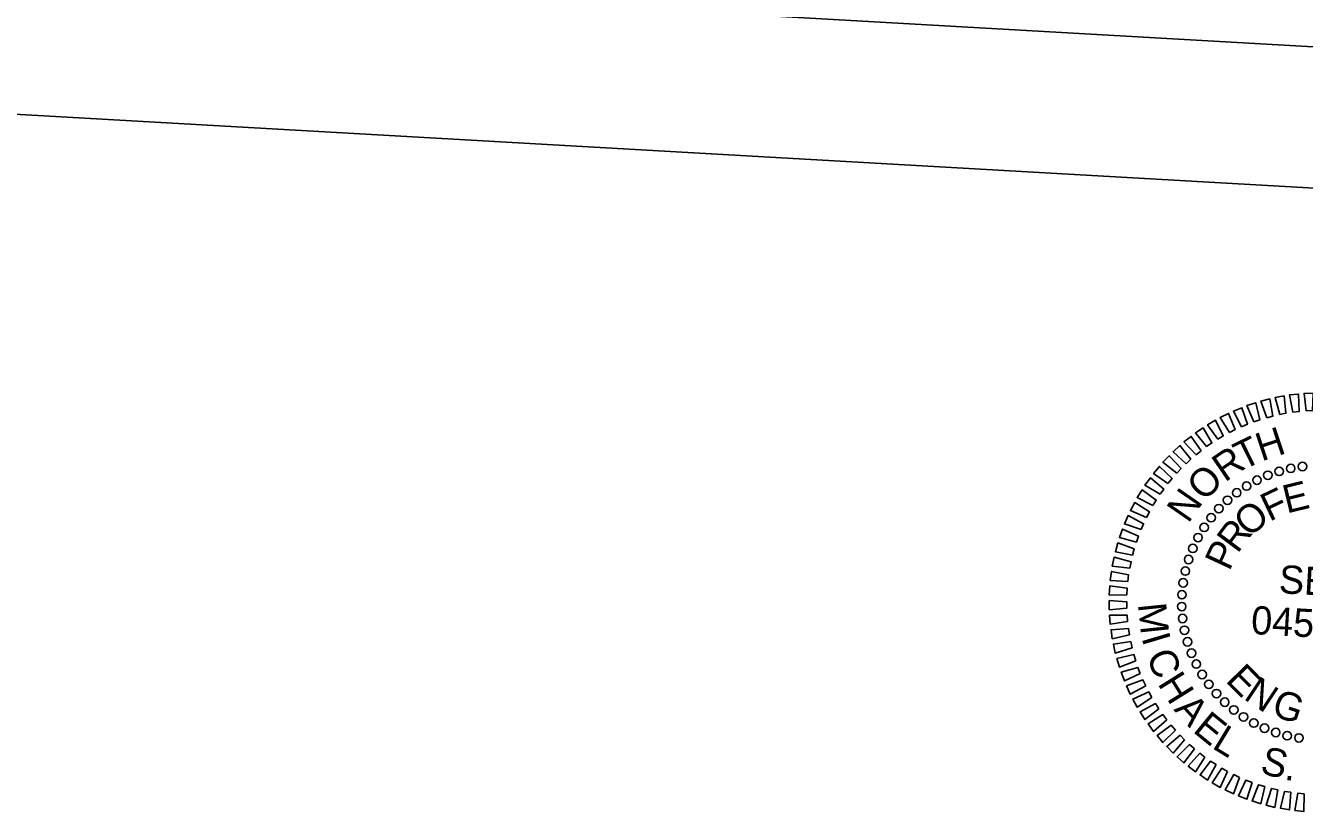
# Model space of a CAD drawing. Extents: x 2601627 to 2606907, y 616646 to 620530.
# Drawn here: x 2605452 to 2606132, y 616647 to 617064 of the extents above; entities that cross this region are included whole.
import ezdxf

# ---------------------------------------------------------------- set-up
doc = ezdxf.new("R2010")
doc.units = 0
for name, color, linetype in [('Sheet PE Seal Cell', 7, 'Continuous'), ('Sheet Title CELL', 7, 'Continuous'), ('Stewart Plot Border Xerox6279 and LJ5000', 7, 'Continuous')]:
    doc.layers.add(name, color=color, linetype=linetype)

msp = doc.modelspace()

# ---------------------------------------------------------------- linework, layer by layer
at = {"layer": 'Sheet PE Seal Cell'}
for points in [[(2606111.46, 616855.96), (2606108.39, 616864.81), (2606113.1, 616865.96), (2606114.76, 616856.85)], [(2606118.37, 616857.65), (2606115.93, 616866.69), (2606120.71, 616867.5), (2606121.73, 616858.31)], [(2606125.39, 616858.85), (2606123.58, 616868.03), (2606128.41, 616868.52), (2606128.79, 616859.27)], [(2606132.47, 616859.55), (2606131.31, 616868.84), (2606136.16, 616868.99), (2606135.89, 616859.74)], [(2606098.06, 616851.16), (2606093.8, 616859.5), (2606098.3, 616861.29), (2606101.21, 616852.51)], [(2606104.67, 616853.8), (2606101, 616862.41), (2606105.62, 616863.88), (2606107.91, 616854.92)], [(2606085.47, 616844.55), (2606080.08, 616852.21), (2606084.29, 616854.62), (2606088.4, 616846.32)], [(2606091.65, 616848.08), (2606086.81, 616856.1), (2606091.18, 616858.2), (2606094.7, 616849.64)], [(2606073.91, 616836.25), (2606067.52, 616843.09), (2606071.35, 616846.05), (2606076.57, 616838.41)], [(2606079.54, 616840.6), (2606073.64, 616847.87), (2606077.67, 616850.56), (2606082.35, 616842.57)], [(2606068.6, 616831.51), (2606061.74, 616837.89), (2606065.36, 616841.12), (2606071.1, 616833.86)], [(2606063.63, 616826.42), (2606056.34, 616832.3), (2606059.73, 616835.77), (2606065.96, 616828.93)], [(2606059.02, 616820.99), (2606051.35, 616826.35), (2606054.48, 616830.05), (2606061.18, 616823.66)], [(2606054.81, 616815.26), (2606046.78, 616820.06), (2606049.65, 616823.97), (2606056.77, 616818.07)], [(2606051.01, 616809.24), (2606042.66, 616813.48), (2606045.25, 616817.58), (2606052.77, 616812.18)], [(2606047.63, 616802.97), (2606039.01, 616806.62), (2606041.31, 616810.89), (2606049.18, 616806.03)], [(2606044.7, 616796.49), (2606035.85, 616799.52), (2606037.84, 616803.94), (2606046.04, 616799.64)], [(2606042.24, 616789.81), (2606033.19, 616792.22), (2606034.87, 616796.77), (2606043.34, 616793.05)], [(2606040.24, 616782.98), (2606031.04, 616784.75), (2606032.4, 616789.4), (2606041.12, 616786.29)], [(2606038.72, 616776.02), (2606029.43, 616777.15), (2606030.46, 616781.89), (2606039.37, 616779.39)], [(2606037.69, 616768.98), (2606028.34, 616769.46), (2606029.04, 616774.25), (2606038.11, 616772.38)], [(2606037.16, 616761.88), (2606027.8, 616761.71), (2606028.16, 616766.54), (2606037.33, 616765.31)], [(2606037.12, 616754.77), (2606027.8, 616753.94), (2606027.82, 616758.78), (2606037.06, 616758.19)], [(2606037.58, 616747.66), (2606028.34, 616746.18), (2606028.02, 616751.02), (2606037.28, 616751.08)], [(2606038.54, 616740.61), (2606029.42, 616738.49), (2606028.77, 616743.29), (2606037.99, 616743.99)], [(2606039.98, 616733.64), (2606031.03, 616730.89), (2606030.05, 616735.64), (2606039.2, 616736.98)], [(2606041.91, 616726.79), (2606033.17, 616723.42), (2606031.86, 616728.09), (2606040.9, 616730.06)], [(2606044.31, 616720.09), (2606035.83, 616716.12), (2606034.19, 616720.68), (2606043.07, 616723.28)], [(2606047.17, 616713.57), (2606038.99, 616709.02), (2606037.04, 616713.46), (2606045.71, 616716.67)], [(2606050.48, 616707.27), (2606042.63, 616702.16), (2606040.38, 616706.45), (2606048.81, 616710.26)], [(2606054.22, 616701.21), (2606046.75, 616695.57), (2606044.2, 616699.69), (2606052.34, 616704.08)], [(2606058.37, 616695.43), (2606051.31, 616689.28), (2606048.48, 616693.22), (2606056.3, 616698.17)], [(2606062.92, 616689.96), (2606056.31, 616683.33), (2606053.21, 616687.06), (2606060.66, 616692.54)], [(2606067.83, 616684.81), (2606061.7, 616677.74), (2606058.35, 616681.24), (2606065.41, 616687.23)], [(2606073.1, 616680.02), (2606067.48, 616672.53), (2606063.89, 616675.8), (2606070.51, 616682.26)], [(2606078.68, 616675.61), (2606073.6, 616667.75), (2606069.79, 616670.75), (2606075.94, 616677.67)], [(2606084.56, 616671.6), (2606080.04, 616663.4), (2606076.03, 616666.13), (2606081.69, 616673.46)], [(2606090.71, 616668.01), (2606086.77, 616659.52), (2606082.58, 616661.96), (2606087.71, 616669.66)], [(2606097.09, 616664.85), (2606093.75, 616656.11), (2606089.4, 616658.26), (2606093.98, 616666.3)], [(2606103.67, 616662.15), (2606100.95, 616653.2), (2606096.47, 616655.04), (2606100.47, 616663.38)], [(2606110.43, 616659.92), (2606108.34, 616650.79), (2606103.74, 616652.31), (2606107.15, 616660.92)], [(2606117.33, 616658.16), (2606115.88, 616648.91), (2606111.18, 616650.11), (2606113.99, 616658.93)], [(2606124.33, 616656.89), (2606123.53, 616647.56), (2606118.76, 616648.43), (2606120.95, 616657.42)], [(2606131.41, 616656.11), (2606131.26, 616646.75), (2606126.44, 616647.28), (2606127.99, 616656.4)]]:
    msp.add_lwpolyline(points, close=True, dxfattribs=at)
for centre in [(2606130.51, 616830.04), (2606112.1, 616825.37), (2606118.1, 616827.46), (2606124.25, 616829.02), (2606095.53, 616816.09), (2606100.78, 616819.66), (2606106.32, 616822.76), (2606090.62, 616812.08), (2606081.93, 616802.84), (2606086.07, 616807.65), (2606078.22, 616797.69), (2606074.97, 616792.24), (2606072.21, 616786.52), (2606069.96, 616780.59), (2606068.24, 616774.48), (2606066.42, 616761.93), (2606067.06, 616768.24), (2606066.33, 616755.58), (2606066.8, 616749.25), (2606067.82, 616742.99), (2606069.38, 616736.84), (2606071.48, 616730.85), (2606074.08, 616725.06), (2606077.18, 616719.52), (2606080.75, 616714.28), (2606084.77, 616709.36), (2606089.19, 616704.81), (2606094, 616700.67), (2606099.15, 616696.96), (2606104.61, 616693.71), (2606110.32, 616690.96), (2606116.26, 616688.71), (2606122.36, 616686.98), (2606128.6, 616685.8)]:
    msp.add_circle(centre, 2.25, dxfattribs=at)
at = {"layer": 'Sheet Title CELL'}
msp.add_lwpolyline([(2602185.54, 617278.13), (2606618.35, 617025.66)], dxfattribs=at)
at = {"layer": 'Stewart Plot Border Xerox6279 and LJ5000'}
msp.add_lwpolyline([(2601627.15, 617234.85), (2606718.89, 616944.81), (2606906.57, 620239.47), (2601814.82, 620529.51)], close=True, dxfattribs=at)

# ---------------------------------------------------------------- texts
at = {"layer": 'Sheet PE Seal Cell'}
for s, rotation, p in [('T', 26.13052, (2606098.83, 616827.87)), ('H', 18.34129, (2606108.7, 616832.67)), ('R', 34.33917, (2606089.24, 616821.4)), ('O', 45.06435, (2606078.27, 616811.02)), ('N', 55.27477, (2606069.8, 616799.41)), ('F', 25.40415, (2606112.91, 616800.59)), ('E', 13.72621, (2606122.12, 616805)), ('O', 41.21293, (2606102.24, 616791.85)), ('R', 53.31239, (2606095.92, 616783.38)), ('P', 65.07463, (2606091.61, 616774.05)), ('SEAL', 356.74026, (2606117.69, 616762.77)), ('M', 275.85931, (2606043.01, 616756.92)), ('045230', 356.74026, (2606102.89, 616741.07)), ('I', 286.56542, (2606044.85, 616739.09)), ('C', 292.50539, (2606047.29, 616729.44)), ('E', 314.59087, (2606089.17, 616715.99)), ('H', 302.01043, (2606053.23, 616714.68)), ('N', 326.35312, (2606098.73, 616706.7)), ('G', 341.40317, (2606113.39, 616697.98)), ('A', 311.76331, (2606061.77, 616700.77)), ('E', 320.8108, (2606071.7, 616689.32)), ('L', 328.79067, (2606081.86, 616680.64)), ('S', 346.14214, (2606107.47, 616667.09)), ('.', 354.25546, (2606120.59, 616663.54))]:
    msp.add_text(s, height=15, rotation=rotation, dxfattribs=at).set_placement(p)

doc.saveas('drawing.dxf')
